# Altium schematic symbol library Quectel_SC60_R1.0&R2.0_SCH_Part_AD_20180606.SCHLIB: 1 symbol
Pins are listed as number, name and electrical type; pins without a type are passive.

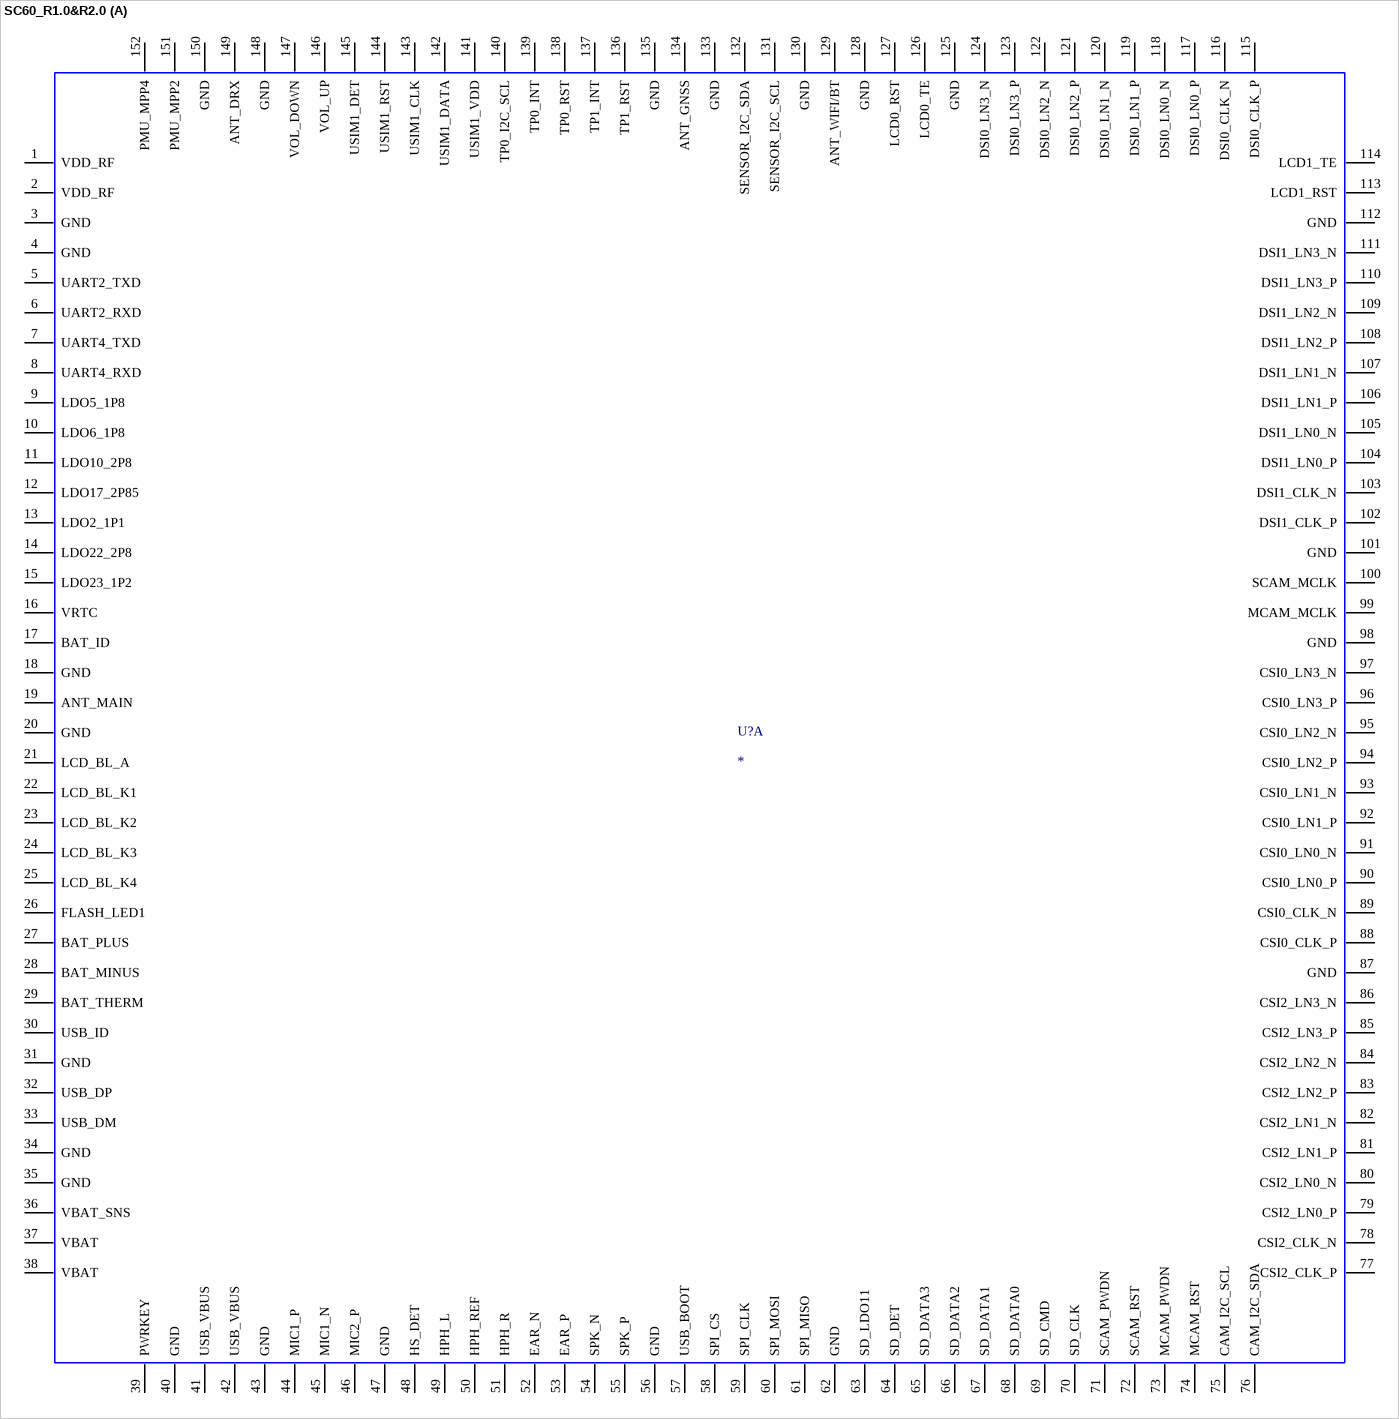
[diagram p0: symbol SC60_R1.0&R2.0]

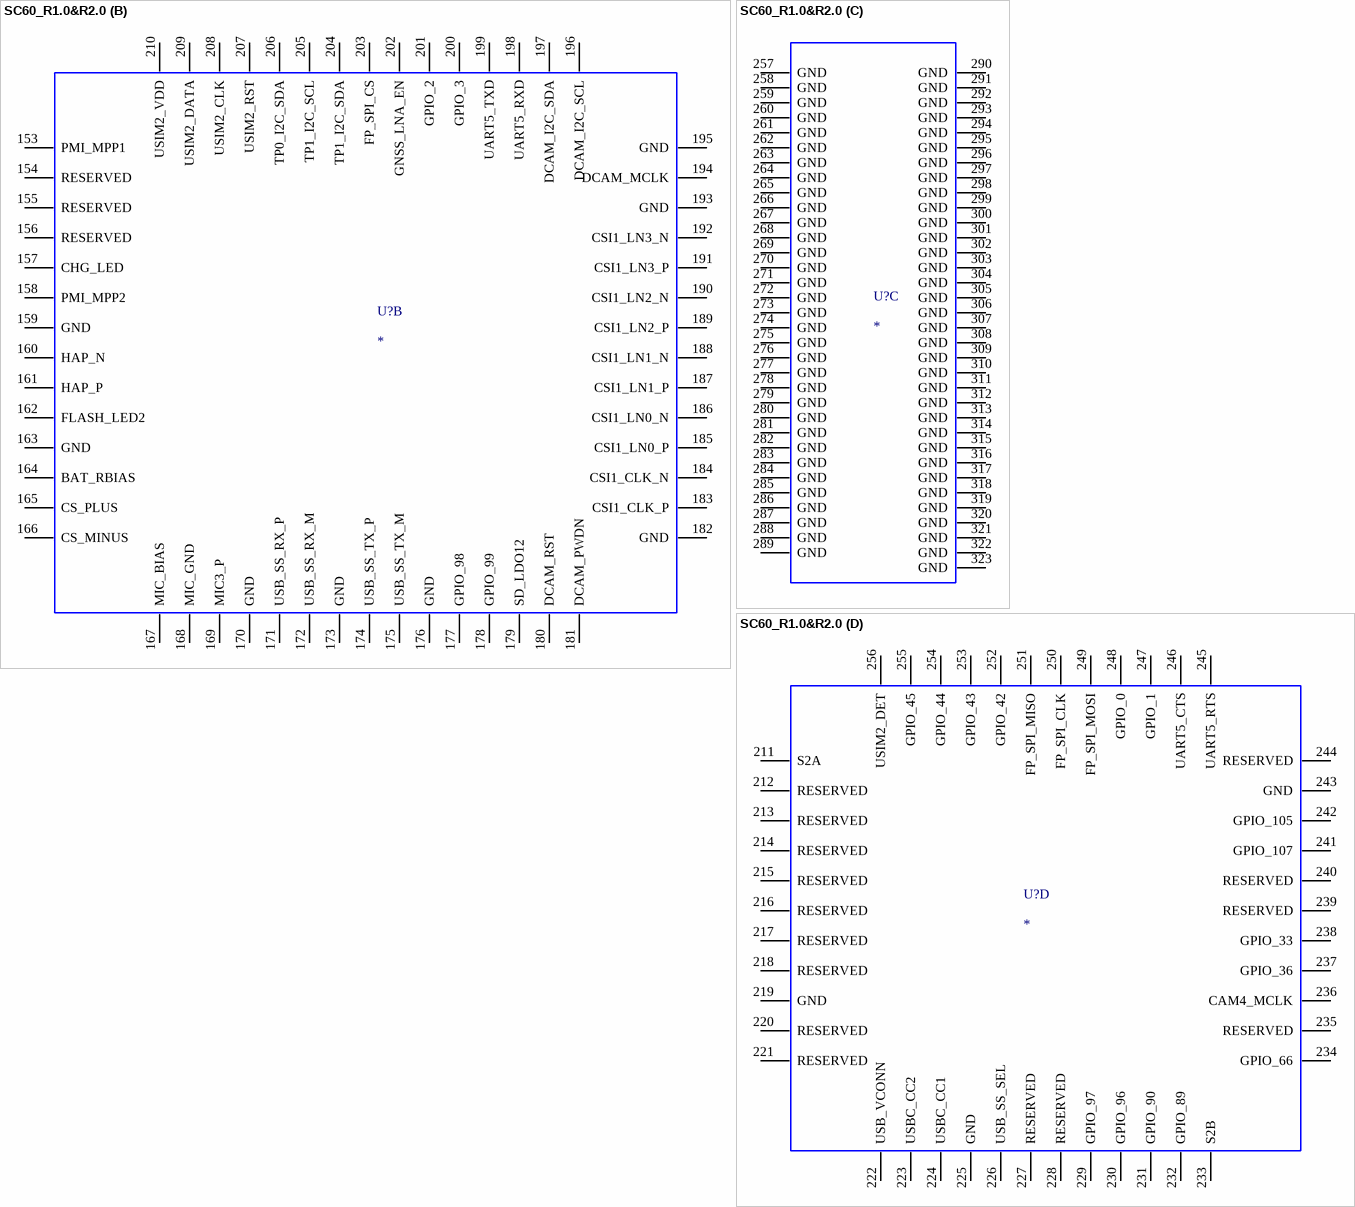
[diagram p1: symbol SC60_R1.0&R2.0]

## SC60_R1.0&R2.0
designator U?
part A pins: 1 VDD_RF, 2 VDD_RF, 3 GND, 4 GND, 5 UART2_TXD, 6 UART2_RXD, 7 UART4_TXD, 8 UART4_RXD, 9 LDO5_1P8, 10 LDO6_1P8, 11 LDO10_2P8, 12 LDO17_2P85, 13 LDO2_1P1, 14 LDO22_2P8, 15 LDO23_1P2, 16 VRTC, 17 BAT_ID, 18 GND, 19 ANT_MAIN, 20 GND, 21 LCD_BL_A, 22 LCD_BL_K1, 23 LCD_BL_K2, 24 LCD_BL_K3, 25 LCD_BL_K4, 26 FLASH_LED1, 27 BAT_PLUS, 28 BAT_MINUS, 29 BAT_THERM, 30 USB_ID, 31 GND, 32 USB_DP, 33 USB_DM, 34 GND, 35 GND, 36 VBAT_SNS, 37 VBAT, 38 VBAT, 39 PWRKEY, 40 GND, 41 USB_VBUS, 42 USB_VBUS, 43 GND, 44 MIC1_P, 45 MIC1_N, 46 MIC2_P, 47 GND, 48 HS_DET, 49 HPH_L, 50 HPH_REF, 51 HPH_R, 52 EAR_N, 53 EAR_P, 54 SPK_N, 55 SPK_P, 56 GND, 57 USB_BOOT, 58 SPI_CS, 59 SPI_CLK, 60 SPI_MOSI, 61 SPI_MISO, 62 GND, 63 SD_LDO11, 64 SD_DET, 65 SD_DATA3, 66 SD_DATA2, 67 SD_DATA1, 68 SD_DATA0, 69 SD_CMD, 70 SD_CLK, 71 SCAM_PWDN, 72 SCAM_RST, 73 MCAM_PWDN, 74 MCAM_RST, 75 CAM_I2C_SCL, 76 CAM_I2C_SDA, 77 CSI2_CLK_P, 78 CSI2_CLK_N, 79 CSI2_LN0_P, 80 CSI2_LN0_N, 81 CSI2_LN1_P, 82 CSI2_LN1_N, 83 CSI2_LN2_P, 84 CSI2_LN2_N, 85 CSI2_LN3_P, 86 CSI2_LN3_N, 87 GND, 88 CSI0_CLK_P, 89 CSI0_CLK_N, 90 CSI0_LN0_P, 91 CSI0_LN0_N, 92 CSI0_LN1_P, 93 CSI0_LN1_N, 94 CSI0_LN2_P, 95 CSI0_LN2_N, 96 CSI0_LN3_P, 97 CSI0_LN3_N, 98 GND, 99 MCAM_MCLK, 100 SCAM_MCLK, 101 GND, 102 DSI1_CLK_P, 103 DSI1_CLK_N, 104 DSI1_LN0_P, 105 DSI1_LN0_N, 106 DSI1_LN1_P, 107 DSI1_LN1_N, 108 DSI1_LN2_P, 109 DSI1_LN2_N, 110 DSI1_LN3_P, 111 DSI1_LN3_N, 112 GND, 113 LCD1_RST, 114 LCD1_TE, 115 DSI0_CLK_P, 116 DSI0_CLK_N, 117 DSI0_LN0_P, 118 DSI0_LN0_N, 119 DSI0_LN1_P, 120 DSI0_LN1_N, 121 DSI0_LN2_P, 122 DSI0_LN2_N, 123 DSI0_LN3_P, 124 DSI0_LN3_N, 125 GND, 126 LCD0_TE, 127 LCD0_RST, 128 GND, 129 ANT_WIFI/BT, 130 GND, 131 SENSOR_I2C_SCL, 132 SENSOR_I2C_SDA, 133 GND, 134 ANT_GNSS, 135 GND, 136 TP1_RST, 137 TP1_INT, 138 TP0_RST, 139 TP0_INT, 140 TP0_I2C_SCL, 141 USIM1_VDD, 142 USIM1_DATA, 143 USIM1_CLK, 144 USIM1_RST, 145 USIM1_DET, 146 VOL_UP, 147 VOL_DOWN, 148 GND, 149 ANT_DRX, 150 GND, 151 PMU_MPP2, 152 PMU_MPP4
part B pins: 153 PMI_MPP1, 154 RESERVED, 155 RESERVED, 156 RESERVED, 157 CHG_LED, 158 PMI_MPP2, 159 GND, 160 HAP_N, 161 HAP_P, 162 FLASH_LED2, 163 GND, 164 BAT_RBIAS, 165 CS_PLUS, 166 CS_MINUS, 167 MIC_BIAS, 168 MIC_GND, 169 MIC3_P, 170 GND, 171 USB_SS_RX_P, 172 USB_SS_RX_M, 173 GND, 174 USB_SS_TX_P, 175 USB_SS_TX_M, 176 GND, 177 GPIO_98, 178 GPIO_99, 179 SD_LDO12, 180 DCAM_RST, 181 DCAM_PWDN, 182 GND, 183 CSI1_CLK_P, 184 CSI1_CLK_N, 185 CSI1_LN0_P, 186 CSI1_LN0_N, 187 CSI1_LN1_P, 188 CSI1_LN1_N, 189 CSI1_LN2_P, 190 CSI1_LN2_N, 191 CSI1_LN3_P, 192 CSI1_LN3_N, 193 GND, 194 DCAM_MCLK, 195 GND, 196 DCAM_I2C_SCL, 197 DCAM_I2C_SDA, 198 UART5_RXD, 199 UART5_TXD, 200 GPIO_3, 201 GPIO_2, 202 GNSS_LNA_EN, 203 FP_SPI_CS, 204 TP1_I2C_SDA, 205 TP1_I2C_SCL, 206 TP0_I2C_SDA, 207 USIM2_RST, 208 USIM2_CLK, 209 USIM2_DATA, 210 USIM2_VDD
part C pins: 257 GND, 258 GND, 259 GND, 260 GND, 261 GND, 262 GND, 263 GND, 264 GND, 265 GND, 266 GND, 267 GND, 268 GND, 269 GND, 270 GND, 271 GND, 272 GND, 273 GND, 274 GND, 275 GND, 276 GND, 277 GND, 278 GND, 279 GND, 280 GND, 281 GND, 282 GND, 283 GND, 284 GND, 285 GND, 286 GND, 287 GND, 288 GND, 289 GND, 290 GND, 291 GND, 292 GND, 293 GND, 294 GND, 295 GND, 296 GND, 297 GND, 298 GND, 299 GND, 300 GND, 301 GND, 302 GND, 303 GND, 304 GND, 305 GND, 306 GND, 307 GND, 308 GND, 309 GND, 310 GND, 311 GND, 312 GND, 313 GND, 314 GND, 315 GND, 316 GND, 317 GND, 318 GND, 319 GND, 320 GND, 321 GND, 322 GND, 323 GND
part D pins: 211 S2A, 212 RESERVED, 213 RESERVED, 214 RESERVED, 215 RESERVED, 216 RESERVED, 217 RESERVED, 218 RESERVED, 219 GND, 220 RESERVED, 221 RESERVED, 222 USB_VCONN, 223 USBC_CC2, 224 USBC_CC1, 225 GND, 226 USB_SS_SEL, 227 RESERVED, 228 RESERVED, 229 GPIO_97, 230 GPIO_96, 231 GPIO_90, 232 GPIO_89, 233 S2B, 234 GPIO_66, 235 RESERVED, 236 CAM4_MCLK, 237 GPIO_36, 238 GPIO_33, 239 RESERVED, 240 RESERVED, 241 GPIO_107, 242 GPIO_105, 243 GND, 244 RESERVED, 245 UART5_RTS, 246 UART5_CTS, 247 GPIO_1, 248 GPIO_0, 249 FP_SPI_MOSI, 250 FP_SPI_CLK, 251 FP_SPI_MISO, 252 GPIO_42, 253 GPIO_43, 254 GPIO_44, 255 GPIO_45, 256 USIM2_DET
